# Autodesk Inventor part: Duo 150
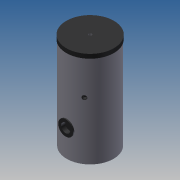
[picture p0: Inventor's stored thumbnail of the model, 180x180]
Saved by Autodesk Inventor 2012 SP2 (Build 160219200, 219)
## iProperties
Created: 2014-05
Part Number: Duo 150
Material: Default
Document SubType Name: Modeling
Designer: michel
Density: 1 g/cm^3
Author: michel
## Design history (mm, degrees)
sketch "Sketch1"
  geometry: C1 r 280 at (0, 0); 1 further point
  constraints: 1 centre point, 1 coincident
  dimensions: "d0" = 560 diameter of C1
extrude "Extrusion1" new body sketch "Sketch1" distance "d1" = 1150; taper "d2" = 0 deg
sketch "Sketch2"
  geometry: L1 (-280, 1150)-(280, 1150) reference; L2 (280, 0)-(280, 1150) reference; L3 (280, 1150)-(280, 1100); L4 (285, 1100)-(285, 1150); L5 (285, 1150)-(280, 1150); L6 (0, -208)-(0, 1248) reference; L7 (285, 1100)-(280, 1100); 1 further point
  constraints: 8 end point, 1 parallel
revolve "Revolution1" sketch "Sketch2" stored, may be unused: angle "d6" = 90 deg
workplane "Work Plane1"
workplane "Work Plane2"
workplane "Work Plane3"
workplane "Work Plane4"
workplane "Work Plane5"
workplane "Work Plane6"
sketch "Sketch3"
  geometry: L1 (404, 985)-(-394, 985) reference; L2 (404, 690)-(-394, 690) reference; L3 (404, 590)-(-394, 590) reference; L4 (404, 245)-(-394, 245) reference; L5 (404, 65)-(-394, 65) reference; L6 (280, 0)-(280, 1100) reference; L7 (290, 985)-(240, 985); L8 (240, 985)-(240, 1001.625); L9 (240, 1001.625)-(290, 1001.625); L10 (290, 1001.625)-(290, 985); L11 (290, 65)-(240, 65); L12 (240, 65)-(240, 81.625); L13 (240, 81.625)-(290, 81.625); L14 (290, 81.625)-(290, 65); L15 (280, 690)-(240, 690); L16 (240, 690)-(240, 700.475); L17 (240, 700.475)-(280, 700.475); L18 (280, 700.475)-(280, 690); L19 (280, 590)-(240, 590); L20 (240, 590)-(240, 606.625); L21 (240, 606.625)-(280, 606.625); L22 (280, 606.625)-(280, 590); L23 (240, 261.625)-(280, 261.625); L24 (280, 261.625)-(280, 245); L25 (280, 245)-(240, 245); L26 (240, 245)-(240, 261.625); 1 further point
  constraints: 40 end point, 8 parallel, 4 point on line, 3 horizontal, 3 perpendicular
  dimensions: "d13" = 50 distance of L8.end L9.end; "d14" = 16.625 distance of L7.end L8.end; "d15" = 50 distance of L12.end L13.end; "d16" = 16.625 distance of L11.end L12.end; "d17" = 40 distance of L16.end L17.end; "d18" = 10.475 distance of L15.end L16.end; "d19" = 40 distance of L20.end L21.end; "d20" = 16.625 distance of L19.end L20.end; "d21" = 40 distance of L23.start L23.end; "d22" = 16.625 distance of L25.end L23.start
revolve "Revolution2" stored, may be unused: angle "d23" = 90 deg
revolve "Revolution3" stored, may be unused: angle "d24" = 90 deg
revolve "Revolution4" stored, may be unused: angle "d25" = 90 deg
revolve "Revolution5" stored, may be unused: angle "d26" = 90 deg
revolve "Revolution6" stored, may be unused: angle "d27" = 90 deg
revolve "Revolution7" stored, may be unused: angle "d28" = 90 deg
revolve "Revolution8" stored, may be unused: angle "d29" = 90 deg
sketch "Sketch4"
  geometry: C1 r 16.625 at (0, 0) reference; C2 r 15.375 at (0, 0); 1 further point
  constraints: 1 centre point, 1 coincident
  dimensions: "d30" = 30.75 diameter of C2
extrude "Extrusion2" cut sketch "Sketch4" distance "d31" = 40; taper "d32" = 0 deg
sketch "Sketch5"
  geometry: C1 r 16.625 at (0, 0) reference; C2 r 15.375 at (0, 0); 1 further point
  constraints: 1 centre point, 1 coincident
  dimensions: "d33" = 30.75 diameter of C2
extrude "Extrusion3" cut sketch "Sketch5" distance "d34" = 40; taper "d35" = 0 deg
workplane "Work Plane7"
sketch "Sketch6"
  geometry: C1 r 9.5 at (0, 0); C2 r 16.625 at (0, -100) reference; C3 r 16.625 at (0, -445) reference; C4 r 15.375 at (0, -100); C5 r 15.375 at (0, -445); 7 further points
  constraints: 6 vertical alignment, 3 centre point, 2 coincident
  dimensions: "d36" = 19 diameter of C1; "d37" = 30.75 diameter of C4; "d38" = 30.75 diameter of C5
  node "Projected Loop1"
  node "Projected Loop2"
extrude "Extrusion4" join sketch "Sketch6" distance "d39" = 40; taper "d40" = 0 deg
extrude "Extrusion5" join sketch "Sketch6" distance "d41" = 40; taper "d42" = 0 deg
extrude "Extrusion6" join sketch "Sketch6" distance "d43" = 40; taper "d44" = 0 deg
workplane "Work Plane8"
workplane "Work Plane9"
sketch "Sketch7"
  geometry: L1 (394.5, 327)-(-407, 327) reference; L2 (-280, 0)-(-280, 1100) reference; L3 (-280, 327)-(-292.5, 327); L4 (-292.5, 327)-(-292.5, 417); L5 (-292.5, 417)-(-280, 417); L6 (-280, 417)-(-280, 327); 1 further point
  constraints: 8 end point, 2 parallel, 2 point on line, 1 horizontal, 1 perpendicular
  dimensions: "d47" = 12.5 distance of L4.end L5.end; "d48" = 90 distance of L3.end L4.end
revolve "Revolution9" sketch "Sketch7" stored, may be unused: angle "d49" = 90 deg
sketch "Sketch8"
  geometry: C1 r 62.5 at (0, 0); A1 r 90 centre (0, 0) between (0, -90) and (0, 90) reference; 1 further point
  constraints: 1 centre point, 1 coincident
  dimensions: "d50" = 125 diameter of C1
extrude "Extrusion7" join sketch "Sketch8" stored distance "d51" = 10; taper "d52" = 0 deg
sketch "Sketch9"
  geometry: C1 r 90 at (0, 0) reference; C2 r 55 at (0, 0); 1 further point
  constraints: 1 centre point, 1 coincident
  dimensions: "d53" = 110 diameter of C2
extrude "Extrusion8" cut sketch "Sketch9" distance "d54" = 50; taper "d55" = 0 deg
sketch "Sketch10"
  geometry: C1 r 285 at (0, 0) reference; C2 r 20.955 at (0, 0); C3 r 19.625 at (0, 0)
  constraints: 2 centre point, 2 coincident
  dimensions: "d56" = 41.91 diameter of C2; "d59" = 39.25 diameter of C3
extrude "Extrusion9" cut sketch "Sketch10" distance "d57" = 50; taper "d58" = 0 deg
extrude "Extrusion10" join sketch "Sketch10" distance "d60" = 50; taper "d61" = 0 deg
workplane "Work Plane10"
sketch "Sketch11"
  geometry: L1 (690, -545.95)-(690, 545.95) reference; L2 (0, 280)-(1100, 280) reference; L3 (690, 280)-(713.9, 280); L4 (713.9, 280)-(713.9, 240); L5 (713.9, 240)-(690, 240); L6 (690, 240)-(690, 280); L7 (667.375, 240)-(667.375, 280); L8 (667.375, 240)-(664.825, 240); L9 (664.825, 240)-(664.825, 280); L10 (667.375, 280)-(664.825, 280); 1 further point
  constraints: 16 end point, 4 perpendicular, 4 point on line, 2 parallel, 1 horizontal
  dimensions: "d63" = 23.9 distance of L4.end L5.end; "d64" = 40 distance of L3.end L4.end; "d67" = 22.625 distance of L5.end L7.start; "d68" = 2.55 distance of L7.start L8.end
revolve "Revolution10" stored, may be unused: angle "d65" = 90 deg
revolve "Revolution11" stored, may be unused: angle "d69" = 90 deg
body "Solid1"
other parameters: "d8" = -65, "d9" = -245, "d12" = 0, "d45" = -327, "d46" = 0, "d62" = 35 deg, "d72" = -985
